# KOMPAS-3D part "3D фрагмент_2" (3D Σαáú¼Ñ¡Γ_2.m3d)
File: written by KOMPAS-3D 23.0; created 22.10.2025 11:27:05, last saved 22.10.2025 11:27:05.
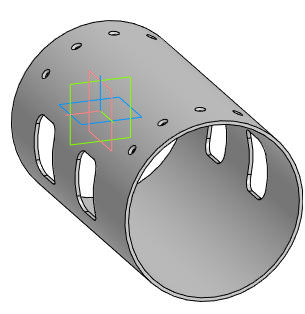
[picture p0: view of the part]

Document properties: Автор: ARM_513_VVK; Полное имя файла: F:\Демо\Демо вариант авиация\3D фрагмент_2.m3d

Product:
- Part/product: 3D фрагмент_2

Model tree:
1. Операция без истории:1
